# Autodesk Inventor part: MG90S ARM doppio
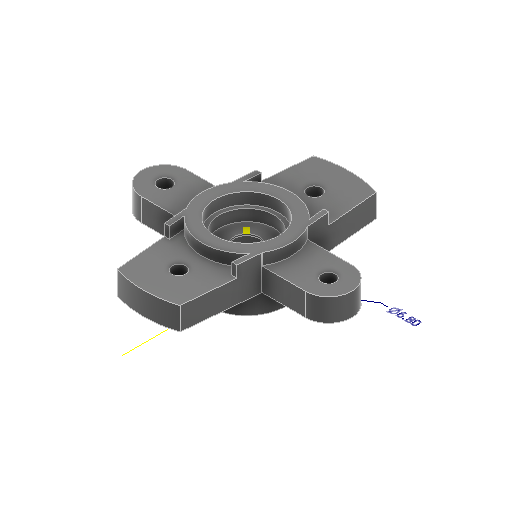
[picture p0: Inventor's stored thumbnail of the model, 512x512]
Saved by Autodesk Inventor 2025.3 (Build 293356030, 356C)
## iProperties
Created: 2026-03
Part Number: MG90S ARM doppio
Material: Generico
Document SubType Name: Modeling
Designer: R5800u
Density: 1 g/cm^3
Appearance: Liscia - Nero
Author: R5800u
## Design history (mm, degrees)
node "Annotazioni"
  node "Quota diametro 4" dims "d44" = 6.8 (derived)
sketch "Schizzo1"
  geometry: C1 r 3.4 at (0, 0); 1 further point
  constraints: 1 centre point, 1 coincident
  dimensions: "d0" = 6.8 diameter of C1
extrude "Estrusione1" new body sketch "Schizzo1" distance "d1" = 4; taper "d2" = 0 deg
sketch "Schizzo2" dims "d4" = 4
  geometry: L1 (0, 0)-(0, 15.5); L2 (-3.398, 0.127)-(-1.992, 15.68); L3 (0, 0)-(-8.473, 0); L4 (0, 0)-(0, -18); L5 (-3.398, -0.127)-(-3.398, 0.127); L6 (3.398, -0.127)-(3.398, 0.127); L7 (3.398, 0.127)-(1.992, 15.68); L8 (-3.386, -0.307)-(-1.767, -18.16); L9 (3.476, 0.685)-(1.767, -18.16); C1 r 3.4 at (0, 0); A1 r 3.4 centre (0, 0) between (-3.398, -0.127) and (-3.398, 0.127) reference; A2 r 1.774 centre (0, -18) between (-1.767, -18.16) and (1.767, -18.16); 11 further points
  constraints: 18 end point, 4 point on circle, 3 coincident, 3 symmetric about line, 3 tangent, 2 centre point, 2 vertical, 1 horizontal, 7 other
  dimensions: "d3" = 15.5 distance of L1.start L1.end; "d57" = 18 distance of L1.start L4.end
extrude "Estrusione2" join sketch "Schizzo2" distance "d5" = 2; taper "d6" = 0 deg
sketch "Schizzo3"
  geometry: C1 r 2.75 at (0, 0); A1 r 3.4 centre (0, 0) between (3.365, 0.485) and (-3.365, 0.485) reference; A2 r 3.4 centre (0, 0) between (3.365, 0.485) and (-3.365, 0.485) reference; A3 r 3.4 centre (0, 0) between (-3.365, 0.485) and (3.365, 0.485); 10 further points
  constraints: 2 centre point, 2 coincident, 1 point on circle
  dimensions: "d7" = 5.5 diameter of C1
extrude "Estrusione3" join sketch "Schizzo3" distance "d8" = 0.01; taper "d9" = 0 deg
sketch "Schizzo5"
  geometry: C1 r 2.75 at (0, 0) reference; 2 further points
  constraints: 1 coincident
hole "Foro1" sketch "Schizzo5" at (0, 0) diameter "d10" = 2.2; stored, may be unused: countersink angle "d14" = 90 deg, drill point angle "d16" = 118 deg; dims "d11" = 6, "d12" = 4.75, "d13" = 1, "d15" = 8
sketch "Schizzo6"
  geometry: C1 r 2.5 at (0, 0); 1 further point
  constraints: 1 centre point, 1 coincident
  dimensions: "d17" = 5 diameter of C1
extrude "Estrusione4" cut sketch "Schizzo6" distance "d18" = 2.85; taper "d19" = 0 deg
sketch "Schizzo7"
  geometry: L1 (-3.386, -0.309)-(-2, -15.5) reference; L2 (1.992, -15.681)-(3.386, -0.307) reference; A1 r 3.4 centre (0, 0) between (-3.386, -0.309) and (3.386, -0.307) reference; A2 r 2 centre (0, -15.5) between (-2, -15.5) and (1.992, -15.681) reference; 2 further points
  constraints: 1 coincident
hole "Foro2" sketch "Schizzo7" at (0, -15.5) diameter "d20" = 1.2; stored, may be unused: countersink angle "d24" = 90 deg, drill point angle "d26" = 118 deg; dims "d21" = 6, "d22" = 4.4, "d23" = 2.3, "d25" = 8
pattern_linear "Serie rettangolare1" dims "d29" = 2.4
mirror "Speculare1"
sketch "Schizzo8"
  geometry: 1 further point
sketch "Schizzo9"
  geometry: C1 r 2.375 at (0, 0) reference; C2 r 8.868 at (0, 0); C3 r 1.1 at (0, 0) reference; C4 r 25.415 at (0, 0); 1 further point
  constraints: 2 centre point, 2 coincident
extrude "Estrusione5" cut sketch "Schizzo9" extent not by distance; stored distance "d32" = 0; taper "d33" = 0 deg
sketch "Schizzo10"
  geometry: L1 (0, 0)-(9, 0); L2 (0.028, 1.9)-(9.028, 1.9); L3 (9.028, 1.9)-(9.028, -1.9); L4 (9.028, -1.9)-(0.028, -1.9); L5 (0.028, -1.9)-(0.028, 1.9); C1 r 3.4 at (0, 0) reference; 2 further points
  constraints: 10 end point, 2 horizontal, 2 parallel, 1 perpendicular, 1 other
  dimensions: "d46" = 3.8 distance of L2.end L3.end; "d69" = 9 distance of L3.end L4.end
extrude "Estrusione6" join sketch "Schizzo10" stored distance "d47" = 4; taper "d48" = 0 deg
fillet "Raccordo1" dims "d49" = 1.9
sketch "Schizzo11"
  geometry: A1 r 1.9 centre (7.128, 0) between (7.128, -1.9) and (7.128, 1.9) reference; 2 further points
  constraints: 1 coincident
hole "Foro3" sketch "Schizzo11" at (7.128, 0) diameter "d50" = 1.2; stored, may be unused: countersink angle "d54" = 90 deg, drill point angle "d56" = 118 deg; dims "d51" = 6, "d52" = 4, "d53" = 2, "d55" = 8
mirror "Speculare2"
sketch "Schizzo12"
  geometry: 1 further point
sketch "Schizzo13"
  geometry: L1 (-7.128, 1.9)-(-3.237, 1.9) reference; L2 (-3.242, -1.9)-(-7.128, -1.9) reference; L3 (-3.242, -1.9)-(-2.646, -8.464) reference; L4 (2.646, -8.464)-(3.242, -1.9) reference; L5 (3.242, -1.9)-(7.128, -1.9) reference; L6 (7.128, 1.9)-(3.237, 1.9) reference; L7 (3.237, 1.9)-(2.644, 8.465) reference; L8 (-2.644, 8.465)-(-3.237, 1.9) reference; L9 (-7.128, 2)-(-3.329, 2); L10 (-3.329, 2)-(-2.738, 8.54); L11 (2.738, 8.54)-(3.329, 2); L12 (3.329, 2)-(7.128, 2); L13 (7.128, -2)-(3.333, -2); L14 (3.333, -2)-(2.74, -8.539); L15 (-2.74, -8.539)-(-3.333, -2); L16 (-3.333, -2)-(-7.128, -2); L17 (3.945, -4.75)-(-3.945, -4.75); L18 (-3.945, -4.75)-(-3.945, 4.75); L19 (-3.945, 4.75)-(3.945, 4.75); L20 (3.945, 4.75)-(3.945, -4.75); L21 (3.945, -4.75)-(-3.945, 4.75); L22 (-3.945, -4.75)-(3.945, 4.75); C1 r 3.85 at (0, 0); C2 r 3.4 at (0, 0) reference; C3 r 0.6 at (-7.128, 0) reference; C4 r 0.6 at (0, 5.9) reference; C5 r 0.6 at (0, -5.9) reference; C6 r 0.6 at (7.128, 0) reference; A1 r 1.1 centre (0, 0) between (-1.1, 0) and (1.1, 0) reference; A2 r 0.6 centre (0, 8.3) between (-0.2, 8.866) and (0.2, 8.866) reference; A3 r 0.6 centre (0, -8.3) between (0.2, -8.866) and (-0.2, -8.866) reference; A4 r 1.9 centre (-7.128, 0) between (-7.128, 1.9) and (-7.128, -1.9) reference; A5 r 8.868 centre (0, 0) between (-2.646, -8.464) and (-0.2, -8.866) reference; A6 r 1.9 centre (7.128, 0) between (7.128, -1.9) and (7.128, 1.9) reference; A7 r 8.868 centre (0, 0) between (0.2, -8.866) and (2.646, -8.464) reference; A8 r 2 centre (-7.128, 0) between (-7.128, 2) and (-7.128, -2); A9 r 8.968 centre (0, 0) between (2.738, 8.54) and (-2.738, 8.54); A10 r 2 centre (7.128, 0) between (7.128, -2) and (7.128, 2); A11 r 8.968 centre (0, 0) between (-2.74, -8.539) and (2.74, -8.539); A12 r 2.75 centre (0, 0) between (-2.75, 0) and (2.75, 0) reference; A13 r 2.75 centre (0, 0) between (2.75, 0) and (-2.75, 0) reference; A14 r 8.868 centre (0, 0) between (2.644, 8.465) and (0.2, 8.866) reference; A15 r 8.868 centre (0, 0) between (-0.2, 8.866) and (-2.644, 8.465) reference; 16 further points
  constraints: 28 end point, 8 point on circle, 5 centre point, 2 coincident, 2 midpoint, 2 parallel, 1 horizontal, 1 horizontal alignment, 1 perpendicular, 13 other
  dimensions: "d58" = 7.7 diameter of C1; "d59" = 0.1 radial gap between concentric circles of A4 A8; "d64" = 9.5 distance of L17.end L18.end
  node "Linea chiusa proiettata2"
extrude "Estrusione7" join sketch "Schizzo13" stored distance "d60" = 10; taper "d61" = 0 deg
extrude "Estrusione8" join sketch "Schizzo13" distance "d62" = 1; taper "d63" = 0 deg
sketch "Schizzo14"
  geometry: L1 (-7.128, -2)-(-3.333, -2) reference; L2 (-3.333, -2)-(-2.74, -8.539) reference; L3 (2.74, -8.539)-(3.333, -2) reference; L4 (3.333, -2)-(7.128, -2) reference; L5 (7.128, 2)-(3.329, 2) reference; L6 (3.329, 2)-(2.738, 8.54) reference; L7 (-2.738, 8.54)-(-3.329, 2) reference; L8 (-3.329, 2)-(-7.128, 2) reference; L9 (-2.335, -8.21)-(-2.938, -1.567); L10 (-2.938, -1.567)-(-7.128, -1.567); L11 (-7.128, 1.567)-(-2.933, 1.567); L12 (-2.933, 1.567)-(-2.333, 8.21); L13 (2.333, 8.21)-(2.933, 1.567); L14 (2.933, 1.567)-(7.128, 1.567); L15 (7.128, -1.567)-(2.938, -1.567); L16 (2.938, -1.567)-(2.335, -8.21); L17 (-3.152, -4)-(3.152, -4); L18 (-3.148, 4)-(3.148, 4); L19 (-3.329, 2)-(-3.329, 1.934); L20 (-3.333, -2)-(-3.333, -1.927); L21 (3.333, -2)-(3.333, -1.927); L22 (3.329, 2)-(3.333, 1.927); C1 r 0.6 at (-7.128, 0) reference; C2 r 0.6 at (0, 5.9) reference; C3 r 0.6 at (0, -5.9) reference; C4 r 0.6 at (7.128, 0) reference; A1 r 3.85 centre (0, 0) between (-3.329, 1.934) and (-3.333, -1.927) reference; A2 r 2 centre (-7.128, 0) between (-7.128, 2) and (-7.128, -2) reference; A3 r 8.968 centre (0, 0) between (-2.74, -8.539) and (2.74, -8.539) reference; A4 r 2 centre (7.128, 0) between (7.128, -2) and (7.128, 2) reference; A5 r 8.968 centre (0, 0) between (2.738, 8.54) and (-2.738, 8.54) reference; A6 r 1.567 centre (-7.128, 0) between (-7.128, 1.567) and (-7.128, -1.567); A7 r 8.535 centre (0, 0) between (2.333, 8.21) and (-2.333, 8.21); A8 r 1.567 centre (7.128, 0) between (7.128, -1.567) and (7.128, 1.567); A9 r 8.535 centre (0, 0) between (-2.335, -8.21) and (2.335, -8.21); 9 further points
  constraints: 28 end point, 12 point on circle, 5 point on line, 4 centre point, 2 parallel, 2 vertical, 1 horizontal, 11 other
  dimensions: "d65" = 4 distance from line of point (0, 0) L18; "d66" = 4 distance from line of point (0, 0) L17
extrude "Estrusione9" join sketch "Schizzo14" stored distance "d67" = 0.4; taper "d68" = 0 deg
node "Solido1"
node "Linea chiusa proiettata1"
node "Linea chiusa proiettata3"
other parameters: "d43" = 57.41156 (derived)
